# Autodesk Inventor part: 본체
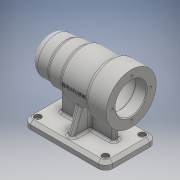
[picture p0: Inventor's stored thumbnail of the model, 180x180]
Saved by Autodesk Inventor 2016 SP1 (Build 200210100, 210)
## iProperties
Created: 2016-06
Part Number: 본체
Material: 일반
Document SubType Name: Modeling
Designer: basic
Density: 1 g/cm^3
Appearance: 기본값
Author: basic
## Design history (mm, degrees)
sketch "스케치1"
  geometry: L1 (56, 0)-(-56, 0); L2 (56, 0)-(56, 15); L3 (46, 25)-(31, 25); L4 (31, 25)-(31, 27); L5 (31, 27)-(11, 27); L6 (11, 27)-(11, 30); L7 (11, 30)-(-28, 30); L8 (-28, 30)-(-28, 34); L9 (-28, 34)-(-56, 34); L10 (-56, 34)-(-56, 0); L11 (-56, 21)-(-41, 21); L12 (-41, 21)-(-41, 21); L13 (-38, 24)-(10, 24); L14 (13, 21)-(13, 21); L15 (13, 21)-(25, 21); L16 (25, 21)-(25, 17.5); L17 (25, 17.5)-(43, 17.5); L18 (43, 17.5)-(43, 16); L19 (43, 16)-(47, 16); L20 (47, 16)-(47, 10.5); L21 (47, 10.5)-(47, 10.5); L22 (50, 7.5)-(50, 0); A1 r 10 centre (46, 15) between (56, 15) and (46, 25); A2 r 3 centre (-38, 21) between (-38, 24) and (-41, 21); A3 r 3 centre (10, 21) between (13, 21) and (10, 24); A4 r 3 centre (47, 7.5) between (50, 7.5) and (47, 10.5); 6 further points
  constraints: 44 end point, 17 perpendicular, 12 point on line, 8 point on circle, 8 tangent, 4 centre point, 2 equal radius, 2 horizontal, 2 vertical, 1 coincident, 1 midpoint
  dimensions: "d0" = 112 distance of L1.start L1.end; "d1" = 25 distance of point (56, 25) L3.end; "d3" = 45 distance between parallel lines of L6 L2; "d4" = 84 distance between parallel lines of L8 L2; "d5" = 50 diameter of L3 L1; "d6" = 68 diameter of L9 L1; "d7" = 60 diameter of L7 L1; "d8" = 54 diameter of L5 L1; "d9" = 10 radius of A1; "d10" = 42 diameter of L11 L1; "d11" = 48 diameter of L13 L1; "d12" = 35 diameter of L17 L1; "d13" = 32 diameter of L19 L1; "d14" = 21 diameter of L21 L1; "d15" = 15 distance of L11.start L11.end; "d16" = 54 distance of point (-41, 24) point (13, 24); "d17" = 12 distance of L14.end L15.end; "d18" = 18 distance of L16.end L17.end; "d19" = 3 distance of L20.end point (50, 10.5); "d20" = 4 distance of L18.end L19.end; "d21" = 3 radius of A2
revolve "회전1" sketch "스케치1" stored, may be unused: angle "d22" = 90 deg
chamfer "모따기1" distance "d23" = 1; stored, may be unused: second distance "d24" = 2, angle "d25" = 45 deg
node "작업 평면1"
sketch "스케치2"
  geometry: L1 (46, -35)-(-46, -35); L2 (-56, -25)-(-56, 25); L3 (-46, 35)-(46, 35); L4 (56, 25)-(56, -25); L5 (56, -35)-(-56, 35); L6 (-56, -35)-(56, 35); A1 r 10 centre (-46, -25) between (-56, -25) and (-46, -35); A2 r 10 centre (46, -25) between (46, -35) and (56, -25); A3 r 10 centre (46, 25) between (56, 25) and (46, 35); A4 r 10 centre (-46, 25) between (-46, 35) and (-56, 25); 1 further point
  constraints: 12 end point, 8 point on circle, 8 point on line, 8 tangent, 4 centre point, 3 equal radius, 2 midpoint, 2 parallel, 1 horizontal, 1 perpendicular
  dimensions: "d27" = 70 distance of L6.start L5.end; "d28" = 112 distance of L5.start L6.start; "d29" = 10 radius of A1
extrude "돌출1" join sketch "스케치2" distance "d30" = 10; taper "d31" = 0 deg
sketch "스케치4"
  geometry: L1 (-56, 25)-(-56, -25) reference; L2 (-36, -4)-(36, -4); L3 (36, -4)-(36, 4); L4 (36, 4)-(-36, 4); L5 (-36, 4)-(-36, -4); L6 (-36, -4)-(36, 4); L7 (36, -4)-(-36, 4); 1 further point
  constraints: 12 end point, 2 midpoint, 2 parallel, 1 horizontal, 1 perpendicular
  dimensions: "d36" = 20 distance between parallel lines of L1 L5; "d37" = 8 distance of L2.end L3.end
extrude "돌출3" join sketch "스케치4" stored distance "d38" = 8; taper "d39" = 0 deg
sketch "스케치6"
  geometry: L1 (-35, -70)-(-35, -60) reference; L2 (-35, -60)-(-4, -60) reference; L3 (-4, -60)-(-4, -29.732) reference; L4 (4, -29.732)-(4, -60) reference; L5 (4, -60)-(35, -60) reference; L6 (35, -60)-(35, -70) reference; L7 (35, -70)-(-35, -70) reference; L8 (-28, -60)-(-15.509, -25.68); C1 r 24 at (0, 0) reference; A1 r 30 centre (0, 0) between (4, -29.732) and (-4, -29.732) reference; 1 further point
  constraints: 2 end point, 1 point on circle, 1 point on line
  dimensions: "d41" = 7 distance from line of L1 L8.start; "d42" = 20 deg angle of L1 L8
feature "리브1" sketch "스케치6" dims "d43" = 1, "d44" = 8, "d45" = 0, "d46" = 0, "d47" = 1, "d48" = 1
chamfer "모따기2" distance "d49" = 4; stored, may be unused: second distance "d50" = 2, angle "d51" = 45 deg
sketch "스케치8"
  geometry: A1 r 6 centre (-46, -25) between (-52, -25) and (-46, -31) reference; 2 further points
  constraints: 1 coincident
hole "구멍1" sketch "스케치8" at (-46, -25) diameter "d52" = 5; stored, may be unused: countersink angle "d56" = 90 deg, drill point angle "d58" = 118 deg; dims "d53" = 6, "d54" = 9, "d55" = 4, "d57" = 8
fillet "모깎기1" dims "d59" = 0.3
sketch "스케치9"
  geometry: L1 (0, 0)-(-26, 0); C1 r 22 at (0, 0) reference; 1 further point
  constraints: 2 end point, 1 coincident, 1 horizontal
  dimensions: "d60" = 26 distance of L1.start L1.end
hole "구멍2" sketch "스케치9" at (-26, 0) diameter "d61" = 3.242; stored, may be unused: countersink angle "d65" = 90 deg, drill point angle "d67" = 118 deg; dims "d62" = 8, "d63" = 9, "d64" = 4, "d66" = 11
fillet "모깎기2" dims "d71" = 3
fillet "모깎기3" dims "d72" = 3
fillet "모깎기4" dims "d73" = 3
node "작업 평면3"
sketch "스케치11"
  geometry: L1 (56, 34)-(56, -34) reference; L2 (-46, -70)-(46, -70) reference; 2 further points
  constraints: 1 other
  dimensions: "d77" = 48 distance from line of L1 point (8, 0); "d78" = 0 vertical distance of point (0, 0) point (8, 0)
feature "엠보싱1" sketch "스케치11" dims "d0" = 112, "d1" = 25, "d3" = 45, "d4" = 84, "d5" = 50, "d6" = 68, "d7" = 60, "d8" = 54, "d9" = 10, "d10" = 42, "d11" = 48, "d12" = 35, "d13" = 32, "d14" = 21, "d15" = 15, "d16" = 54, "d17" = 12, "d18" = 18, "d19" = 3, "d20" = 4, "d21" = 3, "d79" = 0.5, "d80" = 0
fillet "모깎기5" dims "d81" = 3
node "솔리드1"
mirror "대칭1"
mirror "대칭2"
mirror "대칭3"
pattern_circular "원형 패턴1" dims angle "d69" = 360 deg
node "절단 모서리 투영2"
other parameters: "d76" = -30.5
